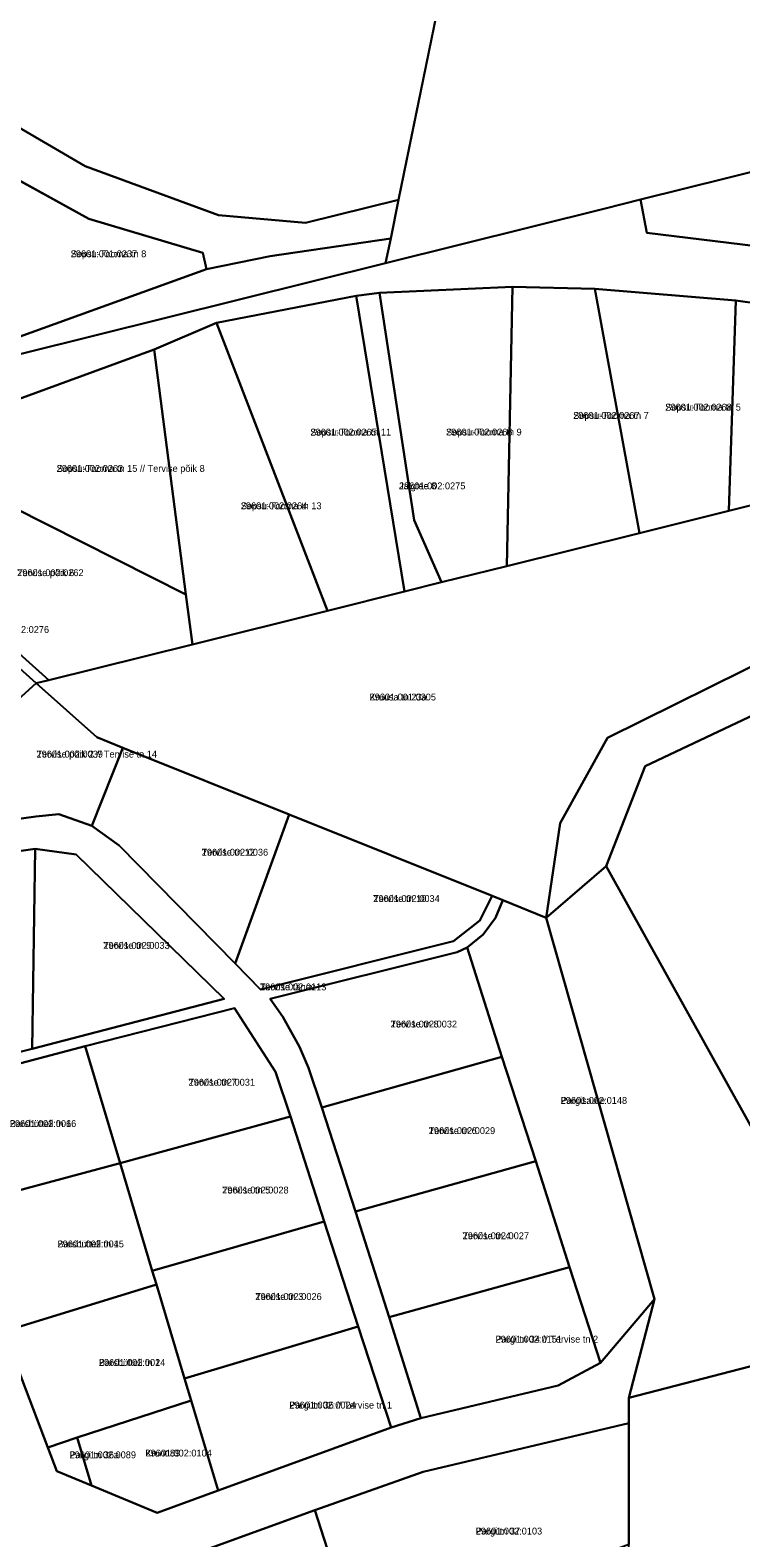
# Model space of a CAD drawing. Extents: x 518839 to 525192, y 6573164 to 6576561.
# Drawn here: x 522644.9 to 522800, y 6574633.7 to 6574963.2 of the extents above; entities that cross this region are included whole.
import ezdxf

# ---------------------------------------------------------------- set-up
doc = ezdxf.new("R2010")
doc.units = 0
for name, color, linetype in [('L_AADRESS', 7, 'Continuous'), ('PIIR', 7, 'Continuous'), ('TUNNUS', 7, 'Continuous')]:
    doc.layers.add(name, color=color, linetype=linetype)

msp = doc.modelspace()

# ---------------------------------------------------------------- linework, layer by layer
at = {"layer": 'PIIR'}
for points in [[(522594.13, 6575277.81), (522653.18, 6575274.63), (522643.43, 6575222.37), (522704.46, 6575214.76), (522708.49, 6575264.65), (522749.68, 6575255.25), (522741.36, 6575209.99), (522734.5, 6575171.21), (522773.81, 6575162.85), (522725.33, 6574926.11), (522705.01, 6574921.1), (522686, 6574922.8), (522656.89, 6574933.47), (522592.43, 6574971.18), (522560.6, 6574995.36)], [(522748.45, 6575038.99), (522794.04, 6575029.6), (522814.7, 6574972.75), (522871.85, 6574992.21), (522897.07, 6574955.8), (522885.59, 6574952.93), (522845, 6574942.81), (522778.15, 6574926.2), (522770.44, 6574924.25), (522722.5, 6574912.3), (522723.6, 6574917.68), (522725.33, 6574926.11)], [(522560.6, 6574995.36), (522592.43, 6574971.18), (522656.89, 6574933.47), (522686, 6574922.8), (522705.01, 6574921.1), (522725.33, 6574926.11), (522723.6, 6574917.68), (522697.29, 6574913.83), (522683.37, 6574910.97), (522682.62, 6574914.53), (522657.66, 6574921.95), (522634.19, 6574934.9), (522608.9, 6574950.59), (522606.14, 6574952.12), (522569.54, 6574975.64), (522558.33, 6574976.27)], [(522778.15, 6574926.2), (522845, 6574942.81), (522842.76, 6574911.21), (522779.52, 6574918.94)], [(522620.02, 6574904.85), (522635.56, 6574934.11), (522657.66, 6574921.95), (522682.62, 6574914.53), (522683.37, 6574910.97), (522633.75, 6574893.05), (522619.24, 6574894.9), (522623.11, 6574903.27)], [(522571.68, 6574906.81), (522566.31, 6574916.86), (522579.51, 6574925), (522618.51, 6574895.01), (522619.24, 6574894.9), (522633.75, 6574893.05), (522683.37, 6574910.97), (522697.29, 6574913.83), (522723.6, 6574917.68), (522722.5, 6574912.3), (522610.95, 6574884.51), (522591.08, 6574901.56)], [(522610.95, 6574884.51), (522722.5, 6574912.3), (522770.44, 6574924.25), (522778.15, 6574926.2), (522779.52, 6574918.94), (522842.76, 6574911.21), (522874.27, 6574905.74), (522901.66, 6574900.58), (522918.07, 6574903.61), (522923.7, 6574889.62), (522911.93, 6574886.68), (522903.89, 6574884.71), (522885.37, 6574890.16), (522824.83, 6574900.51), (522798.96, 6574904.15), (522768.16, 6574906.7), (522750.23, 6574907.13), (522721.17, 6574905.79), (522716.09, 6574905.16), (522685.54, 6574899.26), (522671.97, 6574893.44), (522632.74, 6574879.08), (522620.29, 6574876.47)], [(522685.54, 6574899.26), (522716.09, 6574905.16), (522726.61, 6574840.51), (522709.8, 6574836.32)], [(522716.09, 6574905.16), (522721.17, 6574905.79), (522728.7, 6574856.13), (522734.73, 6574842.53), (522726.61, 6574840.51)], [(522721.17, 6574905.79), (522750.23, 6574907.13), (522748.98, 6574846.08), (522734.73, 6574842.53), (522728.7, 6574856.13)], [(522750.23, 6574907.13), (522768.16, 6574906.7), (522777.93, 6574853.3), (522748.98, 6574846.08)], [(522768.16, 6574906.7), (522798.96, 6574904.15), (522797.41, 6574858.15), (522777.93, 6574853.3)], [(522798.96, 6574904.15), (522824.83, 6574900.51), (522832.37, 6574866.86), (522821.65, 6574864.19), (522797.41, 6574858.15)], [(522671.97, 6574893.44), (522685.54, 6574899.26), (522709.8, 6574836.32), (522680.32, 6574828.97), (522678.89, 6574839.89)], [(522632.74, 6574879.08), (522671.97, 6574893.44), (522678.89, 6574839.89), (522625.88, 6574866.61)], [(522625.88, 6574866.61), (522678.89, 6574839.89), (522680.32, 6574828.97), (522648.95, 6574821.16), (522637.36, 6574831.5), (522612.32, 6574842.43)], [(522646.23, 6574820.48), (522648.95, 6574821.16), (522680.32, 6574828.97), (522709.8, 6574836.32), (522726.61, 6574840.51), (522734.73, 6574842.53), (522748.98, 6574846.08), (522777.93, 6574853.3), (522797.41, 6574858.15), (522821.65, 6574864.19), (522843.3, 6574841.32), (522808.31, 6574827.01), (522770.94, 6574808.51), (522760.62, 6574789.86), (522757.57, 6574769.23), (522748.05, 6574773.06), (522745.73, 6574773.99), (522701.44, 6574791.8), (522665.15, 6574806.38), (522659.43, 6574808.68)], [(522610.9, 6574840.29), (522636.08, 6574829.55), (522646.23, 6574820.48), (522617.74, 6574794.72), (522617.35, 6574801.05), (522610.32, 6574837.29)], [(522612.32, 6574842.43), (522637.36, 6574831.5), (522648.95, 6574821.16), (522646.23, 6574820.48), (522636.08, 6574829.55), (522610.9, 6574840.29)], [(522770.67, 6574780.47), (522805.73, 6574717.38), (522882.5, 6574745.32), (522889.97, 6574753.92), (522860.79, 6574827.49), (522864.94, 6574829.69), (522892.93, 6574757.33), (522904.52, 6574753.38), (522930.28, 6574751.08), (522945.73, 6574752.09), (522949.7, 6574737.65), (522923.91, 6574728.92), (522927.49, 6574718.55), (522931.04, 6574703.12), (522883.78, 6574691.14), (522834.3, 6574679.53), (522775.6, 6574664.3), (522781.17, 6574685.88), (522757.57, 6574769.23)], [(522779.16, 6574802.37), (522840.33, 6574831.28), (522860.79, 6574827.49), (522889.97, 6574753.92), (522882.5, 6574745.32), (522805.73, 6574717.38), (522770.67, 6574780.47)], [(522617.74, 6574794.72), (522646.23, 6574820.48), (522659.43, 6574808.68), (522665.15, 6574806.38), (522658.32, 6574789.32), (522651.13, 6574791.85), (522646.15, 6574791.36), (522622, 6574787.98)], [(522665.15, 6574806.38), (522701.44, 6574791.8), (522689.66, 6574759.21), (522664.35, 6574784.98), (522658.32, 6574789.32)], [(522701.44, 6574791.8), (522745.73, 6574773.99), (522743.04, 6574768.6), (522737.34, 6574764.07), (522695.21, 6574753.54), (522689.66, 6574759.21)], [(522614.06, 6574779.73), (522645.98, 6574784.28), (522645.34, 6574740.58), (522637.28, 6574738.62), (522632.97, 6574739.81), (522622.99, 6574740.32), (522620.38, 6574739.36)], [(522645.98, 6574784.28), (522654.91, 6574783.03), (522687.25, 6574751.5), (522645.34, 6574740.58)], [(522748.05, 6574773.06), (522757.57, 6574769.23), (522781.17, 6574685.88), (522769.39, 6574671.94), (522762.67, 6574692.88), (522755.29, 6574716.01), (522747.88, 6574738.86), (522740.27, 6574762.75), (522743.77, 6574765.53), (522746.48, 6574769.19)], [(522697.27, 6574751.49), (522738.15, 6574761.67), (522740.27, 6574762.75), (522747.88, 6574738.86), (522708.59, 6574727.72), (522705.68, 6574736.43), (522703.7, 6574741.04), (522700.02, 6574747.57)], [(522656.87, 6574741.18), (522689.47, 6574749.49), (522698.47, 6574735.53), (522701.71, 6574725.82), (522664.53, 6574715.56)], [(522616.78, 6574725.99), (522637.83, 6574736.11), (522656.87, 6574741.18), (522664.53, 6574715.56), (522628.17, 6574705.81), (522620.17, 6574721.68)], [(522708.59, 6574727.72), (522747.88, 6574738.86), (522755.29, 6574716.01), (522715.94, 6574705.02)], [(522664.53, 6574715.56), (522701.71, 6574725.82), (522709.07, 6574702.84), (522671.55, 6574692.09)], [(522628.17, 6574705.81), (522664.53, 6574715.56), (522671.55, 6574692.09), (522672.45, 6574689.08), (522639.16, 6574678.8)], [(522715.94, 6574705.02), (522755.29, 6574716.01), (522762.67, 6574692.88), (522723.28, 6574681.93)], [(522671.55, 6574692.09), (522709.07, 6574702.84), (522716.48, 6574679.91), (522678.6, 6574668.54), (522672.45, 6574689.08)], [(522723.28, 6574681.93), (522762.67, 6574692.88), (522769.39, 6574671.94), (522760.19, 6574666.97), (522730.16, 6574659.86)], [(522639.16, 6574678.8), (522672.45, 6574689.08), (522678.6, 6574668.54), (522680.03, 6574663.75), (522655.16, 6574655.6), (522648.72, 6574653.48)], [(522678.6, 6574668.54), (522716.48, 6574679.91), (522723.74, 6574657.84), (522685.93, 6574644.02), (522680.03, 6574663.75)], [(522775.61, 6574593.31), (522775.6, 6574658.76), (522775.6, 6574664.3), (522834.3, 6574679.53), (522819.17, 6574603.38)], [(522655.16, 6574655.6), (522680.03, 6574663.75), (522685.93, 6574644.02), (522672.62, 6574639.2), (522658.26, 6574645.14)], [(522707.04, 6574639.76), (522730.66, 6574648.12), (522775.6, 6574658.76), (522775.6, 6574632.24), (522739.58, 6574618.74), (522716.54, 6574610.1)], [(522648.72, 6574653.48), (522655.16, 6574655.6), (522658.26, 6574645.14), (522650.7, 6574648.28)], [(522676.15, 6574595.01), (522673.53, 6574627.56), (522707.04, 6574639.76), (522716.54, 6574610.1), (522711.78, 6574608.3)]]:
    msp.add_lwpolyline(points, close=True, dxfattribs=at)
for points in [[(522840.33, 6574831.28), (522779.16, 6574802.37), (522770.67, 6574780.47), (522757.57, 6574769.23), (522760.62, 6574789.86), (522770.94, 6574808.51), (522808.31, 6574827.01)], [(522622, 6574787.98), (522646.15, 6574791.36), (522651.13, 6574791.85), (522658.32, 6574789.32), (522664.35, 6574784.98), (522689.66, 6574759.21), (522695.21, 6574753.54), (522737.34, 6574764.07), (522743.04, 6574768.6), (522745.73, 6574773.99), (522748.05, 6574773.06), (522746.48, 6574769.19), (522743.77, 6574765.53), (522740.27, 6574762.75), (522738.15, 6574761.67), (522697.27, 6574751.49), (522700.02, 6574747.57), (522703.7, 6574741.04), (522705.68, 6574736.43), (522708.59, 6574727.72), (522715.94, 6574705.02), (522723.28, 6574681.93), (522730.16, 6574659.86), (522723.74, 6574657.84), (522716.48, 6574679.91), (522709.07, 6574702.84), (522701.71, 6574725.82), (522698.47, 6574735.53), (522689.47, 6574749.49), (522656.87, 6574741.18), (522637.83, 6574736.11)], [(522637.28, 6574738.62), (522645.34, 6574740.58), (522687.25, 6574751.5), (522654.91, 6574783.03), (522645.98, 6574784.28), (522614.06, 6574779.73)], [(522639.16, 6574678.8), (522648.72, 6574653.48), (522650.7, 6574648.28), (522658.26, 6574645.14), (522672.62, 6574639.2), (522685.93, 6574644.02), (522723.74, 6574657.84), (522730.16, 6574659.86), (522760.19, 6574666.97), (522769.39, 6574671.94), (522781.17, 6574685.88), (522775.6, 6574664.3), (522775.6, 6574658.76), (522730.66, 6574648.12), (522707.04, 6574639.76), (522673.53, 6574627.56)]]:
    msp.add_lwpolyline(points, dxfattribs=at)

# ---------------------------------------------------------------- texts
at = {"layer": 'L_AADRESS'}
for s, p in [('Sopsu-Tooma tn 8', (522653.74, 6574913.58)), ('Sopsu-Tooma tn 7', (522763.45, 6574878.25)), ('Sopsu-Tooma tn 5', (522783.56, 6574880.06)), ('Sopsu-Tooma tn 11', (522706.07, 6574874.6)), ('Sopsu-Tooma tn 9', (522735.7, 6574874.62)), ('Sopsu-Tooma tn 15 // Tervise põik 8', (522650.67, 6574866.67)), ('Jalgtee 8', (522725.41, 6574862.86)), ('Sopsu-Tooma tn 13', (522690.88, 6574858.5)), ('Tervise põik 6', (522642.05, 6574843.88)), ('Kruusa tn 23a', (522718.98, 6574816.71)), ('Tervise põik 2 // Tervise tn 14', (522646.27, 6574804.23)), ('Tervise tn 12', (522682.34, 6574782.79)), ('Tervise tn 10', (522719.8, 6574772.67)), ('Tervise tn 9', (522660.85, 6574762.43)), ('Tervise tänav', (522695.06, 6574753.36)), ('Tervise tn 8', (522723.59, 6574745.24)), ('Tervise tn 7', (522679.47, 6574732.52)), ('Pargisaare', (522760.72, 6574728.55)), ('Barsbütteli tn 6', (522640.45, 6574723.49)), ('Tervise tn 6', (522731.91, 6574721.94)), ('Tervise tn 5', (522686.81, 6574708.96)), ('Barsbütteli tn 4', (522650.85, 6574697.18)), ('Tervise tn 4', (522739.3, 6574698.97)), ('Tervise tn 3', (522694.04, 6574685.69)), ('Pargi tn 34 // Tervise tn 2', (522746.49, 6574676.37)), ('Barsbütteli tn 2', (522659.89, 6574671.28)), ('Pargi tn 36 // Tervise tn 1', (522701.47, 6574661.96)), ('Pargi tn 36a', (522653.49, 6574651.09)), ('Krunt 89', (522670.04, 6574651.48)), ('Pargi tn 37', (522742.17, 6574634.43))]:
    msp.add_text(s, height=1.5, dxfattribs=at).set_placement(p)
at = {"layer": 'TUNNUS'}
for s, p in [('29601:001:0237', (522653.74, 6574913.58)), ('29601:002:0267', (522763.45, 6574878.25)), ('29601:002:0268', (522783.56, 6574880.06)), ('29601:002:0265', (522706.07, 6574874.6)), ('29601:002:0266', (522735.7, 6574874.62)), ('29601:002:0263', (522650.67, 6574866.67)), ('29601:002:0275', (522725.41, 6574862.86)), ('29601:002:0264', (522690.88, 6574858.5)), ('29601:002:0262', (522642.05, 6574843.88)), ('29601:002:0276', (522634.51, 6574831.46)), ('29601:001:0305', (522718.98, 6574816.71)), ('29601:002:0039', (522646.27, 6574804.23)), ('29601:002:0036', (522682.34, 6574782.79)), ('29601:002:0034', (522719.8, 6574772.67)), ('29601:002:0033', (522660.85, 6574762.43)), ('29601:002:0113', (522695.06, 6574753.36)), ('29601:002:0032', (522723.59, 6574745.24)), ('29601:002:0031', (522679.47, 6574732.52)), ('29601:002:0148', (522760.72, 6574728.55)), ('29601:002:0016', (522640.45, 6574723.49)), ('29601:002:0029', (522731.91, 6574721.94)), ('29601:002:0028', (522686.81, 6574708.96)), ('29601:002:0015', (522650.85, 6574697.18)), ('29601:002:0027', (522739.3, 6574698.97)), ('29601:002:0026', (522694.04, 6574685.69)), ('29601:002:0151', (522746.49, 6574676.37)), ('29601:002:0014', (522659.89, 6574671.28)), ('29601:002:0024', (522701.47, 6574661.96)), ('29601:002:0089', (522653.49, 6574651.09)), ('29601:002:0104', (522670.04, 6574651.48)), ('29601:002:0103', (522742.17, 6574634.43))]:
    msp.add_text(s, height=1.5, dxfattribs=at).set_placement(p)

doc.saveas('drawing.dxf')
